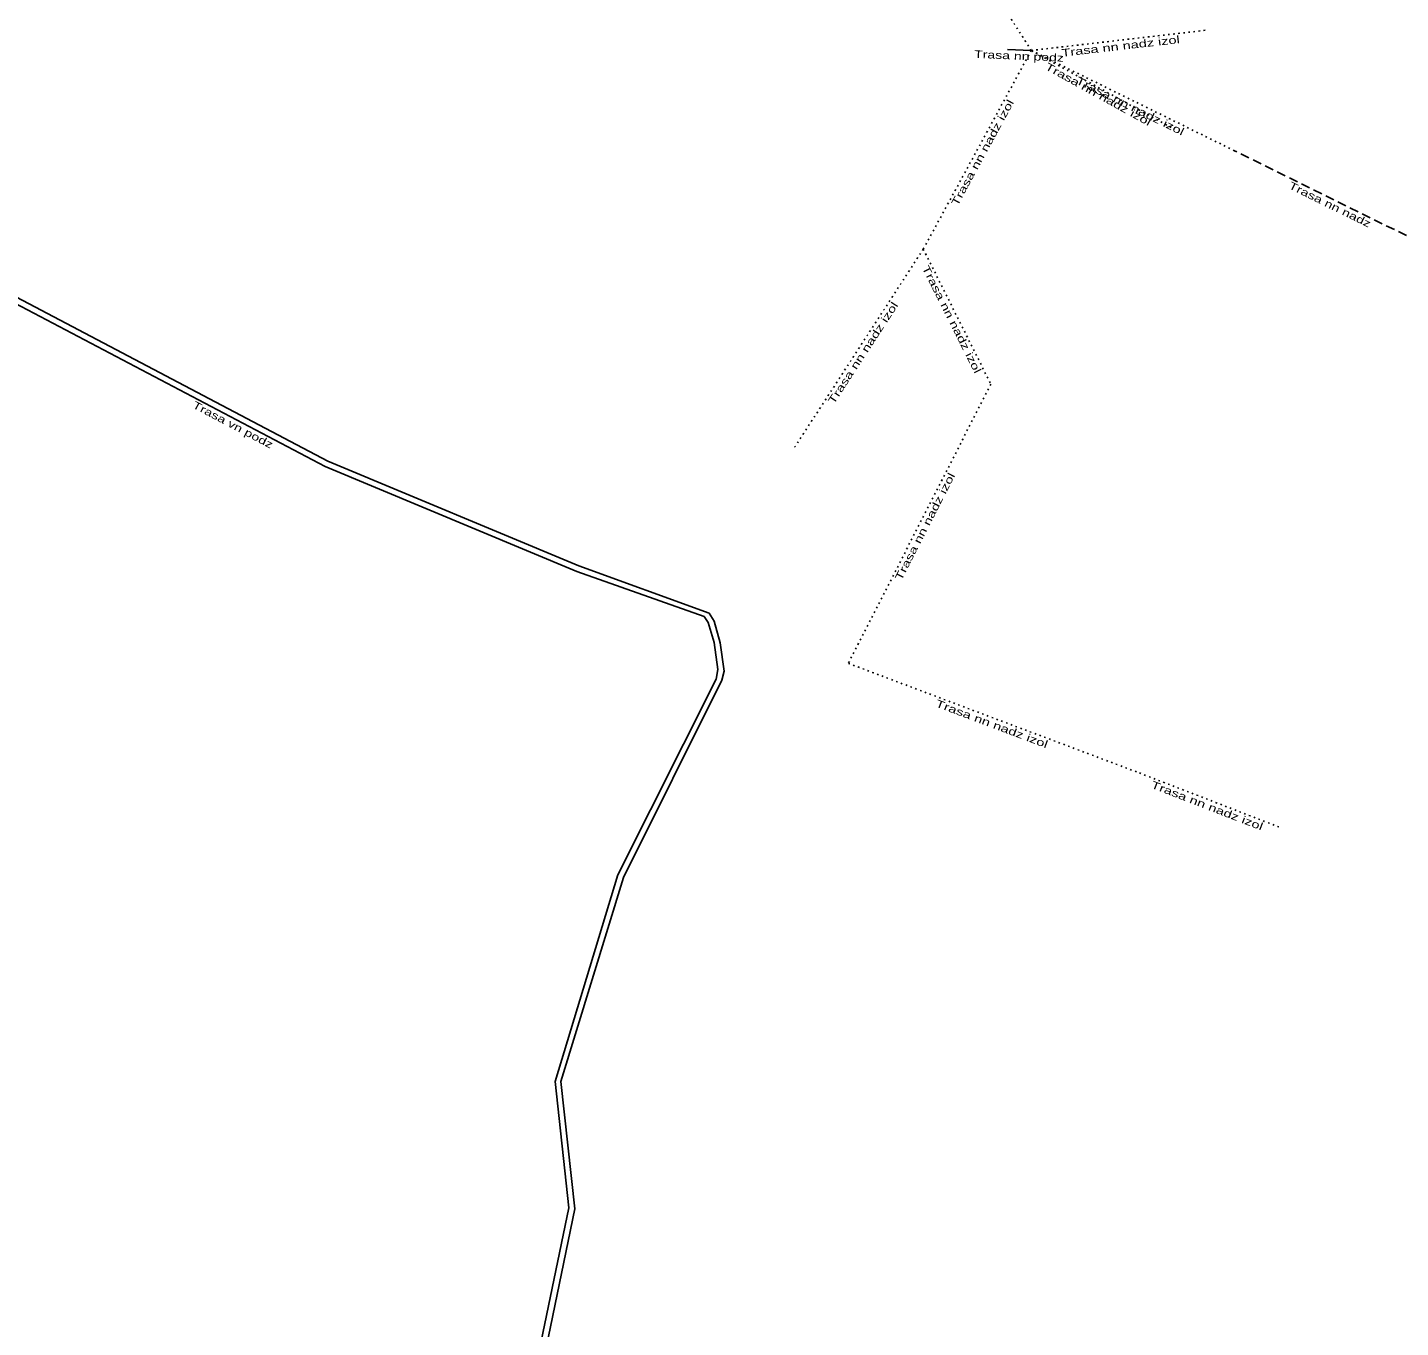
# Model space of a CAD drawing. Extents: x -733620 to -732615, y -1025255 to -1024617.
# Drawn here: x -733116.1 to -733024.6, y -1024954.7 to -1024868.1 of the extents above; entities that cross this region are included whole.
import ezdxf
from ezdxf.enums import TextEntityAlignment as Align

# ---------------------------------------------------------------- set-up
doc = ezdxf.new("R2010")
doc.units = 0
doc.header["$LTSCALE"] = 0.2
doc.linetypes.add('DOTTED', pattern=[1.5, 0.3, -1.2])
doc.linetypes.add('MEDIUM_DASHED', pattern=[4.5, 3, -1.5])
doc.layers.add('11', color=7, linetype='MEDIUM_DASHED', lineweight=25)
doc.layers.add('21', color=7, linetype='Continuous', lineweight=25)
doc.layers.add('20', color=7, linetype='Continuous')

msp = doc.modelspace()

# ---------------------------------------------------------------- linework, layer by layer
at = {"layer": '11', "linetype": 'DOTTED'}
for p, q in [((-733049.21, -1024869.67), (-733056, -1024859)), ((-733049.21, -1024869.67), (-733037.4, -1024868.3)), ((-733049.21, -1024869.67), (-733056.4, -1024882.9)), ((-733035.676, -1024876.348), (-733049.21, -1024869.67)), ((-733049.21, -1024869.67), (-733039.9, -1024874.8)), ((-733056.4, -1024882.9), (-733065.1, -1024896.3)), ((-733056.4, -1024882.9), (-733051.9, -1024891.9)), ((-733051.9, -1024891.9), (-733061.39, -1024910.5)), ((-733061.39, -1024910.5), (-733042, -1024917.8)), ((-733042, -1024917.8), (-733032.7, -1024921.4))]:
    msp.add_line(p, q, dxfattribs=at)
at = {"layer": '11', "linetype": 'Continuous'}
msp.add_line((-733049.21, -1024869.67), (-733050.8, -1024869.6), dxfattribs=at)
at = {"layer": '11'}
msp.add_line((-733022.6, -1024882.8), (-733035.676, -1024876.348), dxfattribs=at)
at = {"layer": '21'}
for points in [[(-733064.167, -1024976.484), (-733064.8, -1024976.055), (-733067.669, -1024974.555), (-733074.425, -1024971.891), (-733081.614, -1024968.561), (-733083.346, -1024967.839), (-733083.705, -1024967.4), (-733083.732, -1024966.753), (-733083.299, -1024964.717), (-733079.617, -1024946.843), (-733080.539, -1024938.355), (-733076.37, -1024924.754), (-733069.811, -1024911.621), (-733069.674, -1024911.019), (-733069.929, -1024909.134), (-733070.34, -1024907.685), (-733070.671, -1024907.144), (-733079.339, -1024904.001), (-733096.073, -1024897.023), (-733123.483, -1024882.599)], [(-733123.677, -1024882.949), (-733096.243, -1024897.385), (-733079.479, -1024904.377), (-733071.002, -1024907.369), (-733070.737, -1024907.783), (-733070.324, -1024909.114), (-733070.084, -1024910.916), (-733070.205, -1024911.541), (-733076.757, -1024924.596), (-733080.92, -1024938.342), (-733080.014, -1024946.778), (-733084.821, -1024970.004), (-733084.893, -1024978.341), (-733085.743, -1024986.047), (-733086.354, -1024987.367), (-733086.948, -1024988.155), (-733095.2, -1024988.87), (-733109.097, -1024989.335), (-733112.927, -1024989.335), (-733113.099, -1024989.174), (-733114.199, -1024984.103), (-733114.673, -1024983.212)]]:
    msp.add_lwpolyline(points, dxfattribs=at)

# ---------------------------------------------------------------- texts
at = {"layer": '20'}
for s, rotation, width, p in [('Trasa nn nadz izol', 6.617, 1.45, (-733043.2293, -1024869.6298)), ('Trasa nn podz', 357.479, 1.4, (-733050.0335, -1024870.2843)), ('Trasa nn nadz izol', 331.144, 1.45, (-733044.8682, -1024872.8033)), ('Trasa nn nadz izol', 333.737, 1.45, (-733042.7301, -1024873.5916)), ('Trasa nn nadz izol', 61.478, 1.45, (-733052.2341, -1024876.5949)), ('Trasa nn nadz', 333.737, 1.4, (-733029.4251, -1024880.1569)), ('Trasa nn nadz izol', 296.565, 1.45, (-733054.7317, -1024887.6897)), ('Trasa nn nadz izol', 57.006, 1.45, (-733060.2051, -1024889.9536)), ('Trasa vn podz', 332.246, 1.4, (-733102.5019, -1024894.825)), ('Trasa nn nadz izol', 62.969, 1.45, (-733056.0657, -1024901.4951)), ('Trasa nn nadz izol', 339.37, 1.45, (-733051.9236, -1024914.7575)), ('Trasa nn nadz izol', 338.839, 1.45, (-733037.5837, -1024920.2055))]:
    msp.add_text(s, height=0.5, rotation=rotation, dxfattribs=dict(at, width=width)).set_placement(p, align=Align.CENTER)

doc.saveas('drawing.dxf')
